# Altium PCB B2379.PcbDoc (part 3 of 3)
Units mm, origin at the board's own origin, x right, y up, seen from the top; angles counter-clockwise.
Board outline 50 x 95 mm, 4 copper layers (Top Layer 1 Signal, Layer 2, Layer 3, Bottom Layer 4 Signal), stack 1.536 mm thick; 177 components, 121 nets, 523 pads, 969 vias.
Unrouted connection lines stored in the file: 25.
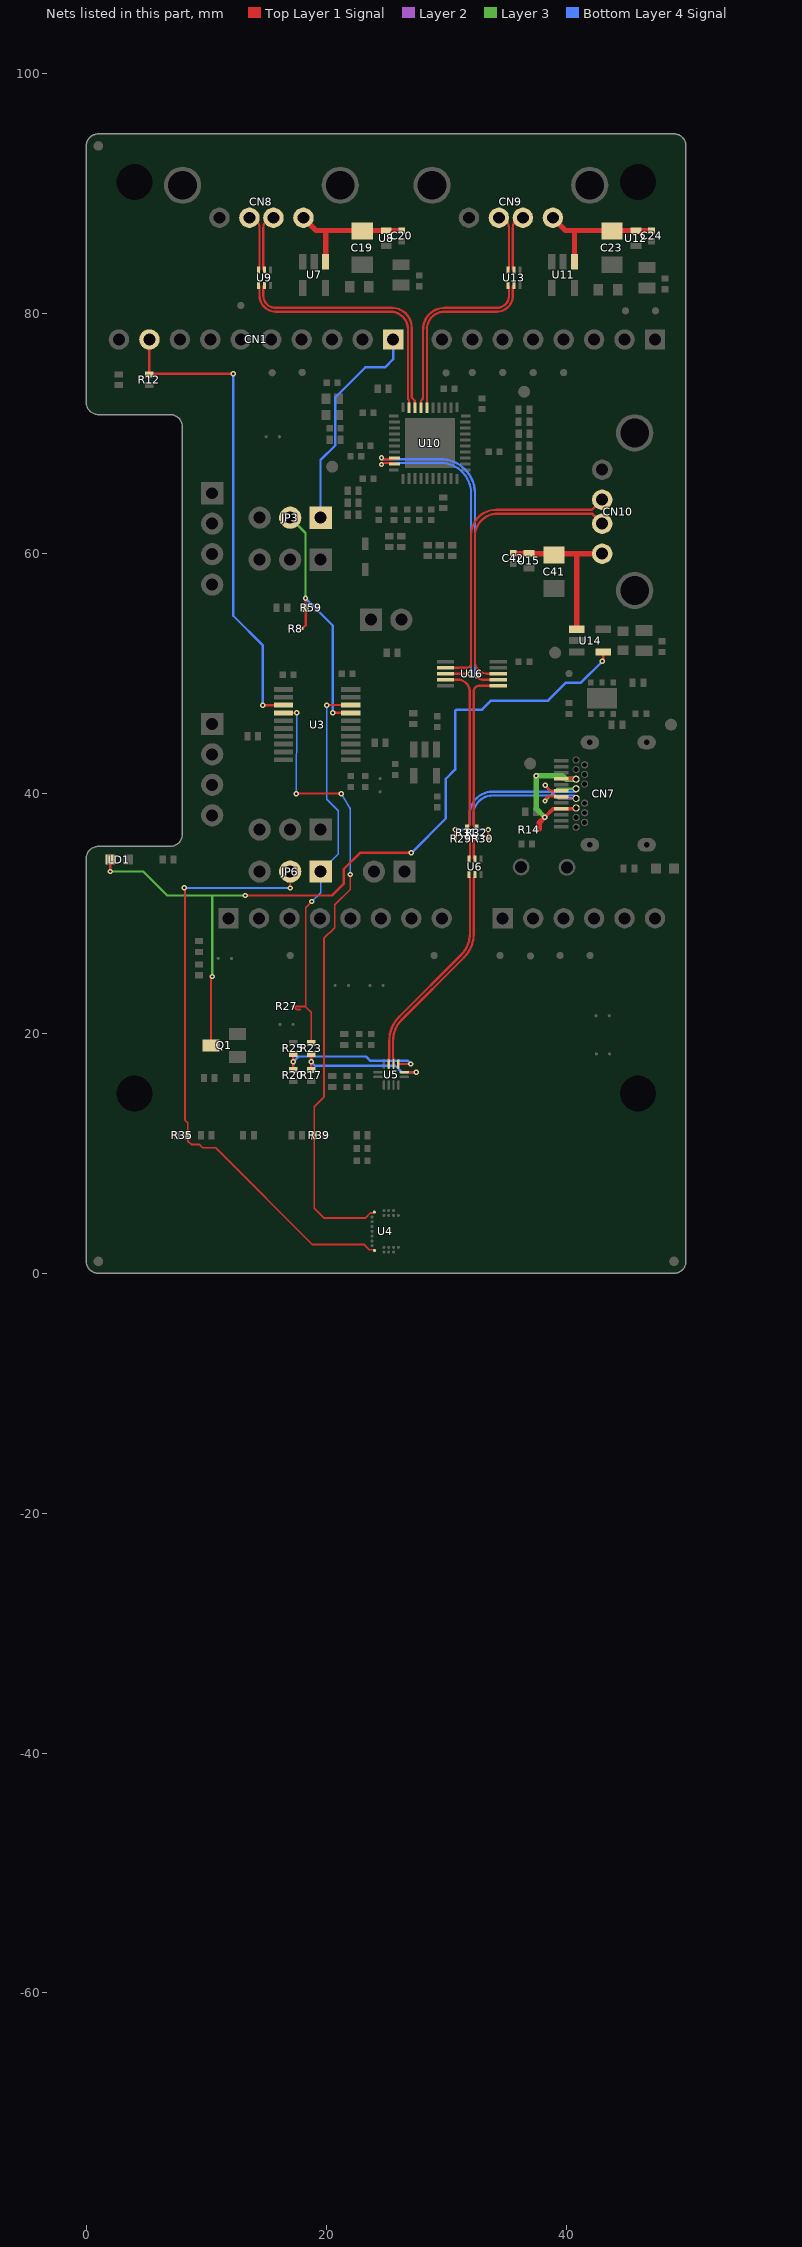
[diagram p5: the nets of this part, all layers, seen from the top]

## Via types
v1: diameter 0.45, hole 0.2, Top Layer 1 Signal to Bottom Layer 4 Signal, tented both sides, 933 vias
v2: diameter 0.45, hole 0.2, Top Layer 1 Signal to Bottom Layer 4 Signal, tented bottom, 24 vias
v3: diameter 0.45/0/0/0.45 (per signal layer), hole 0.2, Top Layer 1 Signal to Bottom Layer 4 Signal, tented both sides, 12 vias

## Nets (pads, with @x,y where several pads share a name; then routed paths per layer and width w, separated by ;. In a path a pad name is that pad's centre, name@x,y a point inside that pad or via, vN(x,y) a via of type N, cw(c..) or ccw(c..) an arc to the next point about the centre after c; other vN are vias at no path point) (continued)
SDA_1V8: JP6.1 R23.1 R27.1 U3.18 | length 33.6
  Top Layer 1 Signal w0.15: 17.827,22 17.603,22 cw(c17.603,22.15) 17.507,22.035 R27.1@17.25,22.25 18.25,22.25 18.298,22.298 ; R23.1@18.75,19.2 18.75,21.75 18.298,22.202 18.298,22.298 ; v1(18.806,31) 18.298,30.492 18.298,22.298 ; v1(20.057,47.375) U3.18@22.05,47.375
  Bottom Layer 4 Signal w0.15: v1(18.806,31) 19.54,31.734 JP6.1@19.54,33.5 21,34.96 21,38.568 20.048,39.52 20.048,47.366 v1(20.057,47.375)
SDA_D14_3V3_4: CN1.9 R12.1 U3.3 | length 40.3
  Top Layer 1 Signal w0.2: CN1.9@5.26,77.86 R12.1@5.26,74.95 5.491,74.996 cw(c5.53,74.8) 5.53,75 v1(12.25,75) ; v1(14.725,47.375) U3.3@16.45,47.375
  Bottom Layer 4 Signal w0.2: v1(12.25,75) 12.25,54.825 14.725,52.35 v1(14.725,47.375)
SDA_GPIO3_1V8: JP6.2 R35.1 U4.M2 | length 50.8
  Top Layer 1 Signal w0.15: v1@8.231,32.136 8.231,12.769 8.45,12.55 R35.1@8.45,11.5 8.45,11.025 8.475,11.025 8.75,10.75 9.409,10.75 9.686,10.473 10.777,10.473 11.25,10 18.858,2.392 23.189,2.392 23.608,1.973 23.925,1.973 23.998,1.9 U4.M2@24.025,1.9 ; v1(17,32.125) JP6.2@17,33.5
  Bottom Layer 4 Signal w0.15: v1(8.181,32.136) 8.231,32.136 8.242,32.125 v1(17,32.125)
TX_D8_3V3_4: CN1.1 JP3.1 | length 18.3
  Bottom Layer 4 Signal w0.2: JP3.1@19.54,63 19.525,63.015 19.525,67.8 20.75,69.025 20.75,73.03 23.259,75.539 24.912,75.539 25.58,76.207 CN1.1@25.58,77.86
TX_GPIO0_1V8: R39.1 U3.4 U4.B2 | length 53.2
  Top Layer 1 Signal w0.15: U3.4@16.45,46.725 17.523,46.725 v1(17.548,46.75) ; v1(17.5,40) v1(21.25,40) ; R39.1@18.897,11.46 19,11.225 19,5.436 19.828,4.608 23.27,4.608 23.689,5.027 23.925,5.027 23.998,5.1 U4.B2@24.025,5.1 ; R39.1@18.989,11.5 19.003,11.775 19.003,13.885 19.81,14.693 19.81,27.921 20.717,28.828 20.717,30.717 22,32 v1(22,33.25)
  Bottom Layer 4 Signal w0.15: v1(17.5,40) v1(17.548,46.75) ; v1(21.25,40) 21.979,38.785 cw(c21.85,38.708) 22,38.708 v1(22,33.25)
TX_GPIO0_3V3_4: JP3.2 R8.1 R59.1 U3.17 | length 21.9
  Top Layer 1 Signal w0.2: R8.1@18,53.75 18.3,54.05 18.3,55.15 18.275,55.175 v1(18.275,56.275) ; v1(20.55,46.725) U3.17@22.05,46.725
  Layer 3 w0.2: JP3.2@17,63 18.275,61.725 v1(18.275,56.275)
  Bottom Layer 4 Signal w0.2: v1(18.275,56.275) 20.55,54 v1(20.55,46.725)
USB2_ST60_3_N: R30.2 R32.2 U6.5 | length 1.9
  Top Layer 1 Signal w0.19: U6.5@32.396,34.54 cw(c32.396,34.632) 32.304,34.632 32.304,36.01 cw(c32.546,36.01) R32.2@32.545,36.252
USB2_ST60_3_P: R29.2 R31.2 U6.6 | length 1.9
  Top Layer 1 Signal w0.19: R29.2@31.747,36.25 cw(c31.747,36.01) 31.988,36.01 31.988,34.632 cw(c31.896,34.632) U6.6@31.896,34.54
USB_D_5_N: CN10.2 U16.8 | length 25
  Top Layer 1 Signal w0.19: U16.8@34.35,50 33.418,50 cw(c33.418,51.018) 32.4,51.018 32.4,51.956 32.4,57.242 32.4,61.446 cw(c34.296,61.446) 34.296,63.341 41.926,63.341 42.168,63.342 CN10.2@43.01,62.5
USB_D_5_P: CN10.3 U16.2 | length 25.5
  Top Layer 1 Signal w0.19: U16.2@29.95,50.5 31.759,50.5 ccw(c31.759,50.824) 32.083,50.824 32.083,57.242 32.083,61.577 cw(c34.165,61.577) 34.165,63.658 41.795,63.658 42.169,63.659 CN10.3@43.01,64.5
USB_H1_6_N: U9.2 U10.28 | length 21.5
  Top Layer 1 Signal w0.19: U9.2@14.85,82.35 ccw(c14.85,82.258) 14.758,82.258 14.758,81.525 ccw(c15.784,81.525) 15.784,80.5 25.487,80.5 cw(c25.487,78.852) 27.134,78.852 27.134,73.015 27.388,72.761 U10.28@27.388,72.187
USB_H1_6_P: U9.1 U10.29 | length 21.4
  Top Layer 1 Signal w0.19: U9.1@14.35,82.35 cw(c14.35,82.258) 14.442,82.258 14.442,81.525 ccw(c15.784,81.525) 15.784,80.183 25.355,80.183 cw(c25.355,78.721) 26.817,78.721 26.817,72.884 26.9,72.801 U10.29@26.9,72.175
USB_H2_6_N: U10.26 U13.2 | length 16.2
  Top Layer 1 Signal w0.19: U10.26@28.4,72.175 28.4,78.708 cw(c29.875,78.708) 28.4,78.711 cw(c29.875,78.708) 28.789,79.706 cw(c29.875,78.708) 29.875,80.183 30.36,80.183 ; 30.364,80.183 34.242,80.183 ccw(c34.242,81.5) 35.558,81.5 35.558,82.258 cw(c35.65,82.258) U13.2@35.65,82.35
USB_H2_6_P: U10.27 U13.1 | length 16.3
  Top Layer 1 Signal w0.19: U10.27@27.9,72.175 27.912,72.187 27.912,72.761 28.081,72.931 28.081,78.706 cw(c29.875,78.706) 28.082,78.753 cw(c29.875,78.706) 28.424,79.761 cw(c29.875,78.706) 29.875,80.5 34.242,80.5 ccw(c34.242,81.5) 35.241,81.5 35.241,82.258 ccw(c35.15,82.258) U13.1@35.15,82.35
USB_H_3_N: CN7.A7 CN7.B7 R30.1 | length 17.1
  Top Layer 1 Signal w0.19: v3(33.5,37) 33.5,36.31 R30.1@33.546,36.253 ; v1(38.25,40.68) 38.68,40.25 CN7.A7@39.59,40.25
  Layer 2 w0.19: v1(38.25,40.68) 39.33,39.6 CN7.B7@40.84,39.6
  Bottom Layer 4 Signal w0.19: v3(33.5,37) 32.846,37 cw(c32.846,37.562) 32.283,37.562 32.283,38.254 cw(c33.871,38.254) 32.443,38.947 cw(c33.871,38.254) 33.871,39.842 40.598,39.842 cw(c40.598,39.6) CN7.B7@40.84,39.6
USB_H_3_P: CN7.A6 CN7.B6 R29.1 | length 17.7
  Top Layer 1 Signal w0.19: R29.1@30.747,36.25 30.75,36.253 v3(30.75,37) ; v1(38.246,39.378) 38.25,39.382 38.25,39.5 38.5,39.75 CN7.A6@39.59,39.75
  Layer 3 w0.19: v1(38.246,39.378) 39.268,40.4 CN7.B6@40.84,40.4
  Bottom Layer 4 Signal w0.19: v3(30.75,37) 31.404,37 ccw(c31.404,37.562) 31.966,37.562 31.966,38.254 cw(c33.871,38.254) 33.871,40.158 40.598,40.158 ccw(c40.598,40.4) CN7.B6@40.84,40.4
USB_HUB1_6_N: CN8.2 U9.5 | length 4.9
  Top Layer 1 Signal w0.19: U9.5@14.85,83.65 cw(c14.85,83.742) 14.758,83.742 14.758,87.168 cw(c15.6,87.168) CN8.2@15.6,88.01
USB_HUB1_6_P: CN8.3 U9.6 | length 4.9
  Top Layer 1 Signal w0.19: CN8.3@13.6,88.01 cw(c13.6,87.169) 14.441,87.169 14.441,83.741 cw(c14.35,83.741) U9.6@14.35,83.65
USB_HUB2_6_N: CN9.2 U13.5 | length 4.9
  Top Layer 1 Signal w0.19: U13.5@35.65,83.65 cw(c35.65,83.742) 35.558,83.742 35.558,87.168 cw(c36.4,87.168) CN9.2@36.4,88.01
USB_HUB2_6_P: CN9.3 U13.6 | length 4.9
  Top Layer 1 Signal w0.19: CN9.3@34.4,88.01 cw(c34.4,87.169) 35.241,87.169 35.241,83.741 cw(c35.15,83.741) U13.6@35.15,83.65
USB_HUB_N: U10.38 U16.7 | length 27.9
  Top Layer 1 Signal w0.19: v3(24.616,68.016) ccw(c24.748,68.016) 24.748,67.884 25.609,67.884 ccw(c25.609,67.975) U10.38@25.7,67.975 ; v3(32.53,49.8) 32.689,49.641 ccw(c33.03,49.983) 33.03,49.5 U16.7@34.35,49.5
  Bottom Layer 4 Signal w0.19: v3(24.616,68.016) ccw(c24.746,68.016) 24.746,67.886 29.543,67.886 cw(c29.543,65.029) 32.4,65.029 32.4,49.93 v3(32.53,49.8)
USB_HUB_P: U10.39 U16.3 | length 27.2
  Top Layer 1 Signal w0.19: v3(24.616,67.439) cw(c24.744,67.439) 24.744,67.567 25.609,67.567 cw(c25.609,67.475) U10.39@25.7,67.475 ; U16.3@29.95,50 v3(31.953,50)
  Bottom Layer 4 Signal w0.19: v3(24.616,67.439) cw(c24.746,67.439) 24.746,67.569 29.543,67.569 cw(c29.543,65.029) 32.083,65.029 v3@32.083,50
USB_SCL_1V8_3: R20.1 R25.2 U5.7 | length 12.7
  Top Layer 1 Signal w0.2: R20.1@17.25,16.95 v1(17.25,17.626) R25.2@17.25,18.302 ; U5.7@26.015,17.45 v1(27.065,17.45)
  Bottom Layer 4 Signal w0.2: v1(17.25,17.626) 17.701,18.077 23.315,18.077 23.657,17.735 26.78,17.735 v1(27.065,17.45)
USB_SDA_1V8_3: R17.1 R23.2 U5.6 | length 11.2
  Top Layer 1 Signal w0.2: R17.1@18.75,16.95 v1(18.75,17.625) R23.2@18.75,18.3 ; U5.6@26.798,16.775 27.475,16.775 v1(27.5,16.75)
  Bottom Layer 4 Signal w0.2: v1(18.75,17.625) 19.075,17.3 25.765,17.3 26.315,16.75 v1(27.5,16.75)
USB_ST60_E_3_N: U5.8 U6.2 | length 18.4
  Top Layer 1 Signal w0.19: U5.8@25.615,17.45 25.613,17.452 25.613,17.868 ccw(c25.546,17.868) 25.593,17.916 cw(c25.641,17.964) 25.573,17.964 25.573,19.373 cw(c28.113,19.373) 26.317,21.169 31.504,26.356 ccw(c29.574,28.286) 32.304,28.286 32.304,32.908 cw(c32.461,32.908) 32.35,33.019 ccw(c32.239,33.13) 32.396,33.13 U6.2@32.396,33.24
USB_ST60_E_3_P: U5.9 U6.1 | length 18.4
  Top Layer 1 Signal w0.19: U5.9@25.215,17.45 25.217,17.452 25.217,17.868 cw(c25.284,17.868) 25.237,17.916 ccw(c25.189,17.964) 25.257,17.964 25.257,19.374 cw(c28.11,19.374) 26.092,21.392 31.243,26.543 ccw(c29.447,28.339) 31.987,28.339 31.987,32.91 ccw(c31.832,32.91) 31.941,33.02 cw(c32.051,33.129) 31.896,33.129 U6.1@31.896,33.24
USB_ST60_N: R32.1 U16.6 | length 13.7
  Top Layer 1 Signal w0.19: R32.1@32.545,37.252 cw(c32.545,37.501) 32.296,37.501 32.296,48.5 cw(c32.796,48.5) 32.796,49 U16.6@34.35,49
USB_ST60_P: R31.1 U16.4 | length 14
  Top Layer 1 Signal w0.19: U16.4@29.95,49.5 30.979,49.5 cw(c30.979,48.5) 31.979,48.5 31.979,37.494 cw(c31.737,37.494) R31.1@31.737,37.252
VBUS_D_5: C41.2 C42.2 CN10.1 U14.1 U15.1 | length 13.6
  Top Layer 1 Signal w0.45: C42.2@35.6,60.05 35.625,60.05 35.675,60 40.93,60 CN10.1@43.01,60 ; U14.1@40.9,53.7 40.9,59.884
VBUS_D_EN_N: LD1.2 Q1.3 U14.4 | length 69.8
  Top Layer 1 Signal w0.2: v1(2,33.5) 2,34.125 LD1.2@2,34.5 ; Q1.3@10.4,19 10.4,24.65 v1(10.5,24.75) ; v1(13.25,31.5) 20.493,31.5 21.455,32.462 21.455,33.689 22.816,35.05 v1(27.102,35.05) ; v1(43.017,51.025) 43.1,51.108 U14.4@43.1,51.8
  Layer 3 w0.2: v1(2,33.5) 4.75,33.5 6.75,31.5 10.5,31.5 ; v1(10.5,24.75) 10.5,31.5 ; v1(13.25,31.5) 10.5,31.5
  Bottom Layer 4 Signal w0.2: v1(27.102,35.05) 29.975,37.923 29.975,41.225 30.75,42 30.75,46.883 30.867,47 33,47 33.75,47.75 38.5,47.75 40,49.25 41.242,49.25 v1(43.017,51.025)
VBUS_HUB1_6: C19.2 C20.2 CN8.1 U7.1 U8.1 | length 11.1
  Top Layer 1 Signal w0.45: CN8.1@18.1,88.01 19.16,86.95 C20.2@26.3,86.95 ; U7.1@19.95,84.35 19.95,86.847
VBUS_HUB2_6: C23.2 C24.2 CN9.1 U11.1 U12.1 | length 11.2
  Top Layer 1 Signal w0.45: CN9.1@38.9,88.01 39.96,86.95 C24.2@47.125,86.95 ; U11.1@40.7,84.35 40.7,86.888
VBUS_POWER_3: CN7.A4 CN7.A9 CN7.B4 CN7.B9 R14.1 | length 12.7
  Top Layer 1 Signal w0.3: 37.7,37 37.75,37.05 ; v1(38.224,38.026) 38.948,38.75 CN7.A4@39.59,38.75 40.79,38.75 CN7.B9@40.84,38.8 ; CN7.A9@39.59,41.25 40.79,41.25 CN7.B4@40.84,41.2
  Top Layer 1 Signal w0.45: 37.75,37.05 37.75,37.552 v1(38.224,38.026)
  Layer 3 w0.45: v1(38.224,38.026) 37.5,38.75 v1(37.5,41.5) 39.7,41.5 40,41.2 CN7.B4@40.84,41.2
pads on no net: CN1.8 CN2.1 CN2.2 CN4.5 CN4.6 CN7.A2 CN7.A3 CN7.A10 CN7.A11 CN7.B2 CN7.B3 CN7.B10 CN7.B11 HW3.1 HW4.1 HW5.1 R61.1 R61.2 R62.1 R62.2 U1.5 U6.4 U9.4 U10.21 U10.22 U10.23 U10.24 U13.4

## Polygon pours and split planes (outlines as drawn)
GND on Layer 3 "GND_L03_P028" (solid, remove dead copper, pour order 28): 1,0 cw(c1,1) 0,1 0,34.597 cw(c1,34.597) 1,35.597 7,35.597 ccw(c7,36.597) 8,36.597 8,70.597 ccw(c7,70.597) 7,71.597 1,71.597 cw(c1,72.597) 0,72.597 0,94 cw(c1,94) 1,95 49,95 cw(c49,94) 50,94 50,1 cw(c49,1) 49,0
GND on Top Layer 1 Signal "GND_L01_P026" (solid, remove dead copper, pour order 26): 1,0 cw(c1,1) 0,1 0,34.597 cw(c1,34.597) 1,35.597 7,35.597 ccw(c7,36.597) 8,36.597 8,70.597 ccw(c7,70.597) 7,71.597 1,71.597 cw(c1,72.597) 0,72.597 0,94 cw(c1,94) 1,95 49,95 cw(c49,94) 50,94 50,1 cw(c49,1) 49,0
GND on Layer 2 "GND_L02_P027" (solid, remove dead copper, pour order 27): 1,0 cw(c1,1) 0,1 0,34.597 cw(c1,34.597) 1,35.597 7,35.597 ccw(c7,36.597) 8,36.597 8,70.597 ccw(c7,70.597) 7,71.597 1,71.597 cw(c1,72.597) 0,72.597 0,94 cw(c1,94) 1,95 49,95 cw(c49,94) 50,94 50,1 cw(c49,1) 49,0
GND on Bottom Layer 4 Signal "GND_L04_P029" (solid, remove dead copper, pour order 29): 1,0 cw(c1,1) 0,1 0,34.597 cw(c1,34.597) 1,35.597 7,35.597 ccw(c7,36.597) 8,36.597 8,70.597 ccw(c7,70.597) 7,71.597 1,71.597 cw(c1,72.597) 0,72.597 0,94 cw(c1,94) 1,95 49,95 cw(c49,94) 50,94 50,1 cw(c49,1) 49,0

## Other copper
Top Layer 1 Signal:
  drawing of 20 lines, arcs and shapes, not listed
  text "1" at 4.75,28.75 h0.75
  text ".Layer_Name" at -11.637,-69.423 h3
  text ".GTL" at 30.058,-69.423 h3
Layer 2:
  pour cut-out: 38.262,41.037 38.276,41.039 38.364,41.022 38.385,41.007 38.411,41.002 38.486,40.952 38.5,40.931 38.522,40.916 38.572,40.841 38.577,40.816 38.591,40.794 38.609,40.706 38.604,40.68 38.609,40.655 38.609,40.654 39.428,39.835 40.477,39.835 40.514,39.89 40.536,39.904 40.55,39.926 40.65,39.992 40.675,39.997 40.697,40.012 40.814,40.035 40.84,40.03 40.866,40.035 40.983,40.012 41.005,39.997 41.03,39.992 41.13,39.926 41.144,39.904 41.166,39.89 41.232,39.79 41.237,39.765 41.252,39.743 41.275,39.626 41.27,39.6 41.275,39.574 41.252,39.457 41.237,39.435 41.232,39.41 41.166,39.31 41.144,39.296 41.13,39.274 41.03,39.208 41.005,39.203 40.983,39.188 40.866,39.165 40.84,39.17 40.814,39.165 40.697,39.188 40.675,39.203 40.65,39.208 40.55,39.274 40.536,39.296 40.514,39.31 40.477,39.365 39.33,39.365 39.306,39.375 39.28,39.375 39.207,39.405 39.189,39.424 39.164,39.434 38.277,40.322 38.276,40.322 38.25,40.327 38.224,40.322 38.136,40.339 38.115,40.354 38.089,40.359 38.014,40.408 38,40.43 37.978,40.445 37.928,40.519 37.923,40.545 37.909,40.567 37.891,40.655 37.896,40.68 37.891,40.706 37.909,40.794 37.923,40.816 37.928,40.841 37.978,40.916 38,40.931 38.014,40.952 38.089,41.002 38.115,41.007 38.136,41.022 38.224,41.039 38.238,41.037 38.25,41.042
  pour cut-out: 30.467,36.529 31.028,36.529 31.029,36.529 31.029,35.969 30.468,35.969
  pour cut-out: 33.246,35.97 33.248,35.971 33.248,36.53 33.801,36.53 33.802,36.531 33.808,36.526 33.808,35.972
  pour cut-out: 32.246,36.194 32.245,36.195 32.245,36.533 32.818,36.533 32.814,36.529 32.814,35.971 32.399,35.971
  pour cut-out: 32.256,36.975 32.254,36.973 32.255,36.973 32.815,36.973 32.815,37.532 32.813,37.531 32.409,37.531 32.391,37.512 32.256,37.309
  pour cut-out: 32.011,36.533 32.027,36.425 32.027,36.195 31.879,35.973 31.789,35.973 31.604,35.973 31.457,35.973 31.457,36.531 31.458,36.532 32.012,36.532
  pour cut-out: 31.457,37.53 31.866,37.531 32.017,37.308 32.017,37.122 32.017,36.975 31.459,36.975 31.458,36.976 31.458,37.531
  pour cut-out: 29.952,50.356 29.225,50.355 29.225,50.356 29.225,50.652 30.674,50.652 30.676,50.651 30.674,50.65 30.674,50.355
  pour cut-out: 29.952,49.852 29.225,49.85 29.225,49.852 29.225,50.147 30.674,50.147 30.676,50.146 30.674,50.145 30.674,49.85
  pour cut-out: 29.953,49.355 29.227,49.354 29.227,49.355 29.227,49.651 30.676,49.651 30.677,49.65 30.676,49.649 30.676,49.354
  pour cut-out: 34.354,49.852 33.628,49.851 33.628,49.852 33.628,50.148 35.077,50.148 35.078,50.147 35.077,50.146 35.077,49.851
  pour cut-out: 34.352,49.352 33.625,49.351 33.625,49.352 33.625,49.648 35.075,49.648 35.076,49.647 35.075,49.646 35.075,49.351
  pour cut-out: 34.352,48.853 33.625,48.852 33.625,48.853 33.625,49.149 35.075,49.149 35.076,49.148 35.075,49.147 35.075,48.852
  text "2" at 4.725,27.413 h0.75
  text ".G1" at 30.083,-69.498 h3
  text ".Layer_Name" at -11.612,-69.548 h3
Layer 3:
  pour cut-out: 40.983,40.812 41.005,40.797 41.03,40.792 41.13,40.726 41.144,40.704 41.166,40.69 41.232,40.59 41.237,40.565 41.252,40.543 41.275,40.426 41.27,40.4 41.275,40.374 41.252,40.257 41.237,40.235 41.232,40.21 41.166,40.11 41.144,40.096 41.13,40.074 41.03,40.008 41.005,40.003 40.983,39.988 40.866,39.965 40.84,39.97 40.814,39.965 40.697,39.988 40.675,40.003 40.65,40.008 40.55,40.074 40.536,40.096 40.514,40.11 40.477,40.165 39.365,40.165 38.605,39.405 38.605,39.404 38.6,39.378 38.605,39.352 38.587,39.265 38.573,39.243 38.568,39.217 38.518,39.143 38.496,39.128 38.482,39.106 38.407,39.057 38.381,39.051 38.36,39.037 38.272,39.019 38.246,39.024 38.22,39.019 38.132,39.037 38.111,39.051 38.085,39.057 38.01,39.106 37.996,39.128 37.974,39.143 37.924,39.217 37.919,39.243 37.905,39.265 37.887,39.352 37.892,39.378 37.887,39.404 37.905,39.492 37.919,39.514 37.924,39.539 37.974,39.614 37.996,39.628 38.01,39.65 38.085,39.7 38.111,39.705 38.132,39.72 38.22,39.737 38.234,39.734 38.246,39.74 38.259,39.734 38.272,39.737 38.273,39.737 39.102,40.566 39.126,40.576 39.145,40.595 39.217,40.625 39.244,40.625 39.268,40.635 40.477,40.635 40.514,40.69 40.536,40.704 40.55,40.726 40.65,40.792 40.675,40.797 40.697,40.812 40.814,40.835 40.84,40.83 40.866,40.835
  text "3" at 5.153,25.445 h0.75
  text ".Layer_Name" at -11.612,-69.498 h3
  text ".G2" at 30.083,-69.548 h3
Bottom Layer 4 Signal:
  pour cut-out: 244 vertices and 0 holes, not listed, extent 30.391,36.641 41.275,40.835
  pour cut-out: 177 vertices and 0 holes, not listed, extent 24.768,2.341 26.062,14.861
  pour cut-out: 177 vertices and 0 holes, not listed, extent 24.257,49.441 32.889,68.377
  text "4" at 5.17,24.063 h0.75
  text ".GBL" at 18.879,-69.53 h3
  text ".Layer_Name" at 60.193,-69.53 h3
Multi-Layer:
  pour cut-out: 4.187,23.5 4.187,30 5.687,30 5.687,23.5

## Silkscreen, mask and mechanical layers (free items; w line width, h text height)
Top Overlay:
  drawing of 61 lines, arcs and shapes, not listed
  text "HUB DEVICE 1" at 5.5,84.516 h1.4
  text "HUB DEVICE 2" at 26.5,84.516 h1.4
  text "I" at 1.206,84.439 h8
  text "C" at 7.369,80.586 h5
  text "H" at 1.061,79.835 h8
  text "B2379B" at 6.45,73.275 h2
  text "DEVICE" at 40.5,72.266 h1.4
  text "EXT" at 9.5,69.084 h1.4
  text "UART" at 9.5,68 h1.4
  text "UART" at 15.5,66.025 h1.4
  text "+3V3" at 12,66 h1.2
  text "EXT" at 14.5,65 h1.2
  text "MCU" at 17.35,65 h1.2
  text "Tx" at 11.9,62.25 h1.2
  text "Rx" at 11.875,59.375 h1.2
  text "HUB Disable" at 22.1,56 h1.2
  text "GND" at 9.5,55 h1.2
  text "L" at 33.281,54.204 h8
  text "EXT" at 9.675,49.884 h1.4
  text "I2C" at 9.75,48.75 h1.4
  text "+3V3" at 12,46.75 h1.2
  text "SDA" at 12.05,42.832 h1.2
  text "SCL" at 12.05,40.348 h1.2
  text "I2C" at 16.075,39.975 h1.4
  text "EXT" at 14.5,39 h1.2
  text "MCU" at 17.25,39 h1.2
  text "GND" at 9.5,35.75 h1.2
  text "NUCLEO 5V" at 22,35.5 h1.4
  text "5V" at 33.875,33.55 h1.2
  text "GND" at 41.2,33.55 h1.2
  text "LINK_STATUS" at 1.375,32.575 h1.4
  text "POWER ON" at 42.8,31.75 h1.4
  text "3V3" at 18.55,27.436 h1.2
  text "5V" at 21.25,27.436 h1.2
  text "GND" at 23.375,27.436 h1.2
  text "GND" at 25.95,27.436 h1.2
  text "Product configured" at 37.875,24.313 h1.4
  text "as R61/R62 mounted" at 36.975,23.066 h1.4
  text "X-NUCLEO-60L1A1" at 28.625,21.241 h1.4
  text "Local" at 45.025,21.089 h1.4
  text "XN$60L1A1B" at 30.15,20.055 h1.4
  text "E" at 2.617,18.501 h8
  text "X-NUCLEO-60R1A1" at 28.775,18.091 h1.4
  text "Remote" at 45.05,18.014 h1.4
  text "XN$60R1A1B" at 30.225,16.88 h1.4
  text "ST60 reserved area" at 33.875,7.516 h1.4
  text "G" at 3.668,7.129 h5
  text "S" at 8.75,6.5 h5
  text "R 006-001386" at 12.575,5.625 h1.2
  text "NOT FCC APPROVED FOR RESALE" at 1.625,4.3 h1.6 r90
  text "T" at 37.822,1.965 h8
  text "J" at 6.632,1.411 h10
  text "FOR EVALUATION ONLY" at 2.525,0.55 h1.4
  text ".Layer_Name" at -11.612,-69.498 h3
  text ".GTO" at 30.083,-69.498 h3
Bottom Overlay:
  text ".GBO" at 18.879,-69.53 h2
  text ".Layer_Name" at 60.193,-69.53 h2
Top Paste:
  text ".Layer_Name" at -11.639,-69.488 h3
  text ".GTP" at 30.055,-69.488 h3
Bottom Paste:
  text ".GBP" at 18.77,-69.515 h3
  text ".Layer_Name" at 60.084,-69.515 h3
Top Solder:
  region: 4.187,23.5 4.187,30 5.687,30 5.687,23.5
  text ".Layer_Name" at -11.614,-69.563 h3
  text ".GTS" at 30.08,-69.563 h3
Bottom Solder:
  region: 24.525,13.625 24.525,12.625 23.525,12.625 23.525,13.625
  region: 25.35,13.625 25.35,12.625 25.15,12.625 25.15,13.625
  region: 25.475,10.625 25.475,11.625 25.675,11.625 25.675,10.625
  region: 26.3,10.625 26.3,11.625 27.3,11.625 27.3,10.625
  region: 4.187,23.5 4.187,30 5.687,30 5.687,23.5
  lines w0.3: 16.5,2.3 25,2.25 33.475,2.3 ; 25,0 25,5.5 25,10
  text ".GBS" at 18.795,-69.59 h3
  text ".Layer_Name" at 60.109,-69.59 h3
M1-Board Shape:
  lines w0.05: 17.25,16.167 17.25,16.167
  lines w0.1: 0,34.597 cw(c1,34.597) 1,35.597 ; 0,34.597 cw(c1,34.597) 1,35.597 ; 0,34.597 0,1 ccw(c1,1) 1,0 18.5,0 30,0 49,0 ccw(c49,1) 50,1 50,94 ; 0,72.597 ccw(c1,72.597) 1,71.597 ; 0,72.597 ccw(c1,72.597) 1,71.597 ; 0,72.597 0,94 ; 0,94 cw(c1,94) 1,95 ; 0,94 cw(c1,94) 1,95 ; 1,35.597 7,35.597 ; 1,71.597 7,71.597 ; 1,95 49,95 ; 7,35.597 ccw(c7,36.597) 8,36.597 ; 7,35.597 ccw(c7,36.597) 8,36.597 ; 7,71.597 cw(c7,70.597) 8,70.597 ; 7,71.597 cw(c7,70.597) 8,70.597 ; 8,36.597 8,70.597 ; 49,95 cw(c49,94) 50,94 ; 49,95 cw(c49,94) 50,94
M2-Board Dimensions:
  text ".Layer_Name" at -11.612,-69.498 h3
  text ".GM2" at 30.083,-69.498 h3
M3-Top Dimensions:
  lines w0.1: 49.828,94.753 55.093,100 63.531,100
  text "r=1mmx8" at 55.603,100.477 h1.4
M5-Top Constraints:
  circle w0.254: c4,91 r2.752
  circle w0.254: c46,91 r2.75
  lines w0.254: -30.14,18.73 51.42,18.73 51.42,88.73 -30.14,88.73 -30.14,18.73
  text "M1136 C-04 NUCLEO-L476RG" at -26.957,42.858 h1 r90
M14-Top Assembly:
  text ".Layer_Name" at -11.612,-69.498 h3
  text ".GM14" at 30.083,-69.498 h3
M15-Bottom Assembly:
  text ".GM15" at 18.879,-69.53 h3
  text ".Layer_Name" at 60.193,-69.53 h3
M16-Top Courtyard:
  lines w0.05: 20,0 30.002,0 30.002,9.002 20,9.002 20,0
Drill Drawing:
  drawing of 374 lines, arcs and shapes, not listed
  text "« THE COMPONENTS WITH PLATED THROUGH HOLE (PTH) MAY BE WELDED (CABLED) IN \"PIN-IN-PASTE\" MODE (IF NECESSARY) »" at 92.369,103.254 h3.5
  text "PCB SPECIFICATIONS :" at 76.114,97.194 h3
  text "**Plating type :" at 193.164,96.844 h2.5
  text "X ECU104" at 115.739,93.327 h3
  text "TG-170" at 131.239,93.327 h3
  text "TG-150" at 148.339,93.327 h3
  text "TG-140" at 165.489,93.327 h3
  text "TG-155" at 179.889,93.327 h3
  text "FR-4" at 108.375,93.294 h3
  text "A.   MATERIAL :" at 76.114,93.194 h3
  text "lead Gold" at 199.889,92.369 h2.5
  text "B.   MATERIAL FAMILY :" at 76.114,90.194 h3
  text "N/A" at 114.614,90.194 h3
  text "C.   SOLDERMASK COLOR :" at 76.114,87.194 h3
  text "GREEN" at 114.614,87.194 h3
  text "WHITE" at 131.114,87.194 h3
  text "RED" at 149.364,87.194 h3
  text "X  Blue ink PANTONE 2955" at 165.364,87.194 h3
  text "D.   SILKSCREEN COLOR :" at 76.114,84.194 h3
  text "X  WHITE" at 114.614,84.194 h3
  text "YELLOW" at 131.114,84.194 h3
  text "BLACK" at 149.364,84.194 h3
  text "Blue ink PANTONE 2955" at 165.364,84.194 h3
  text "E.   SURFACE FINISH :" at 76.114,81.194 h3
  text "X  ENIG" at 114.614,81.194 h3
  text "IMMERSION SILVER" at 131.114,81.194 h3
  text "IMMERSION TIN" at 165.364,81.194 h3
  text "HASL" at 114.614,78.194 h3
  text "HASL (PB-FREE)" at 131.114,78.194 h3
  text "GOLDEN FINGER" at 165.364,78.194 h3
  text "F.   IMPEDANCE CONTROL :" at 76.114,75.194 h3
  text "NO" at 114.614,75.194 h3
  text "X  YES  (SEE IMPEDANCE TABLE FOR DETAIL INFORMATION)" at 131.114,75.194 h3
  text "G.   STACK-UP :" at 76.114,69.844 h3
  text "SEE LAYER STACK-UP SEQUENCE FOR OVERALL THICKNESS." at 114.614,69.844 h3
  text "AREL" at 76.966,61.381 h1.52
  text "Name" at 83.528,61.381 h1.52
  text "Material" at 99.799,61.381 h1.52
  text "Thickness" at 114.041,61.381 h1.52
  text "Constant" at 123.145,61.381 h1.52
  text "Board Layer Stack" at 131.572,61.381 h1.52
  text "Top Overlay" at 83.528,58.333 h1.52
  text "Top Solder" at 83.528,55.285 h1.52
  text "SM-003" at 99.799,55.285 h1.52
  text "1.00mil" at 114.041,55.285 h1.52
  text "4" at 123.145,55.285 h1.52
  text "1" at 76.966,52.237 h1.52
  text "Top Layer 1 Signal" at 83.528,52.237 h1.52
  text "Cu EXT" at 99.799,52.237 h1.52
  text "1.38mil" at 114.041,52.237 h1.52
  text "Dielectric 1" at 83.528,49.189 h1.52
  text "2 x 7628" at 99.798,49.189 h1.52
  text "14.17mil" at 114.041,49.189 h1.52
  text "4.6" at 123.145,49.189 h1.52
  text "2" at 76.964,46.141 h1.52
  text "Layer 2" at 83.528,46.141 h1.52
  text "CF-004" at 99.799,46.141 h1.52
  text "0.71mil" at 114.041,46.141 h1.52
  text "Core" at 83.528,43.093 h1.52
  text "CORE- 6 X 7628M" at 99.799,43.093 h1.52
  text "27.95mil" at 114.04,43.093 h1.52
  text "4.4" at 123.145,43.093 h1.52
  text "3" at 76.966,40.045 h1.52
  text "Layer 3" at 83.528,40.045 h1.52
  text "CF-004" at 99.799,40.045 h1.52
  text "0.71mil" at 114.041,40.045 h1.52
  text "Dielectric 2" at 83.528,36.997 h1.52
  text "2 x 7628" at 99.798,36.997 h1.52
  text "14.17mil" at 114.041,36.997 h1.52
  text "4.6" at 123.145,36.997 h1.52
  text "4" at 76.966,33.949 h1.52
  text "Bottom Layer 4 Signal" at 83.528,33.949 h1.52
  text "Cu EXT" at 99.799,33.949 h1.52
  text "1.38mil" at 114.041,33.949 h1.52
  text "Bottom Solder" at 83.528,30.901 h1.52
  text "SM-003" at 99.799,30.901 h1.52
  text "1.00mil" at 114.041,30.901 h1.52
  text "4" at 123.145,30.901 h1.52
  text "Bottom Overlay" at 83.528,27.853 h1.52
  text "Total board thickness:" at 76.966,24.805 h1.52
  text "62.47mil" at 114.041,24.805 h1.52
  text "Symbol" at 76.921,18.679 h1.83
  text "Count" at 84.081,18.679 h1.83
  text "Hole Size" at 92.175,18.679 h1.83
  text "Plated" at 106.846,18.679 h1.83
  text "Hole Type" at 113.132,18.679 h1.83
  text "Drill Layer Pair" at 122.284,18.679 h1.83
  text "Via/Pad" at 150.127,18.679 h1.83
  text "Pad Shape" at 157.626,18.679 h1.83
  text "Template" at 167.422,18.679 h1.83
  text "Description" at 191.92,18.679 h1.83
  text "Hole Tolerance (-)" at 201.758,18.679 h1.83
  text "Hole Length" at 216.646,18.679 h1.83
  text "Routed Path Length" at 230.56,18.679 h1.83
  text "Via Feature" at 246.769,18.679 h1.83
  text "Via Type" at 264.225,18.679 h1.83
  text "945" at 84.081,15.525 h1.52
  text "0.200mm (7.87mil)" at 92.175,15.525 h1.52
  text "PTH" at 106.846,15.525 h1.52
  text "Round" at 113.132,15.525 h1.52
  text "Top Layer 1 Signal - Bottom Layer 4 Signal" at 122.284,15.525 h1.52
  text "Via" at 150.127,15.525 h1.52
  text "Rounded" at 157.626,15.525 h1.52
  text "(Mixed)" at 167.422,15.525 h1.52
  text "(Mixed)" at 191.92,15.525 h1.52
  text "-" at 216.646,15.525 h1.52
  text "-" at 230.56,15.525 h1.52
  text "24" at 84.081,12.371 h1.52
  text "0.200mm (7.87mil)" at 92.175,12.371 h1.52
  text "PTH" at 106.846,12.371 h1.52
  text "Round" at 113.132,12.371 h1.52
  text "Top Layer 1 Signal - Bottom Layer 4 Signal" at 122.284,12.371 h1.52
  text "Via" at 150.127,12.371 h1.52
  text "Rounded" at 157.626,12.371 h1.52
  text "v45h20m-45mx0" at 167.422,12.371 h1.52
  text "-" at 216.646,12.371 h1.52
  text "-" at 230.56,12.371 h1.52
  text "Filling Both, Capping Both" at 246.769,12.371 h1.52
  text "Type 7" at 264.225,12.371 h1.52
  text "14" at 84.081,9.217 h1.52
  text "0.400mm (15.75mil)" at 92.175,9.217 h1.52
  text "PTH" at 106.846,9.217 h1.52
  text "Round" at 113.132,9.217 h1.52
  text "Top Layer 1 Signal - Bottom Layer 4 Signal" at 122.284,9.217 h1.52
  text "Pad" at 150.127,9.217 h1.52
  text "Rounded" at 157.626,9.217 h1.52
  text "c60h40m70" at 167.422,9.217 h1.52
  text "-" at 216.646,9.217 h1.52
  text "-" at 230.56,9.217 h1.52
  text "3" at 84.081,6.063 h1.52
  text "0.450mm (17.72mil)" at 92.175,6.063 h1.52
  text "PTH" at 106.846,6.063 h1.52
  text "Slot" at 113.132,6.063 h1.52
  text "Top Layer 1 Signal - Bottom Layer 4 Signal" at 122.284,6.063 h1.52
  text "Pad" at 150.127,6.063 h1.52
  text "Rounded" at 157.626,6.063 h1.52
  text "r155_115h45_85r57m165_125(Tol-5)" at 167.422,6.063 h1.52
  text "0.050mm (1.97mil)" at 201.758,6.063 h1.52
  text "0.850mm (33.47mil)" at 216.646,6.063 h1.52
  text "0.400mm (15.75mil)" at 230.56,6.063 h1.52
  text "1" at 84.081,2.908 h1.52
  text "0.450mm (17.72mil)" at 92.175,2.908 h1.52
  text "PTH" at 106.846,2.908 h1.52
  text "Slot" at 113.132,2.908 h1.52
  text "Top Layer 1 Signal - Bottom Layer 4 Signal" at 122.284,2.908 h1.52
  text "Pad" at 150.127,2.908 h1.52
  text "Rounded" at 157.626,2.908 h1.52
  text "r155_115h45_85r57m165_125" at 167.422,2.908 h1.52
  text "0.850mm (33.47mil)" at 216.646,2.908 h1.52
  text "0.400mm (15.75mil)" at 230.56,2.908 h1.52
  text "70" at 84.081,-0.246 h1.52
  text "1.000mm (39.37mil)" at 92.175,-0.246 h1.52
  text "PTH" at 106.846,-0.246 h1.52
  text "Round" at 113.132,-0.246 h1.52
  text "Top Layer 1 Signal - Bottom Layer 4 Signal" at 122.284,-0.246 h1.52
  text "Pad" at 150.127,-0.246 h1.52
  text "(Mixed)" at 157.626,-0.246 h1.52
  text "(Mixed)" at 167.422,-0.246 h1.52
  text "-" at 216.646,-0.246 h1.52
  text "-" at 230.56,-0.246 h1.52
  text "6" at 84.081,-3.4 h1.52
  text "2.400mm (94.49mil)" at 92.175,-3.4 h1.52
  text "PTH" at 106.846,-3.4 h1.52
  text "Round" at 113.132,-3.4 h1.52
  text "Top Layer 1 Signal - Bottom Layer 4 Signal" at 122.284,-3.4 h1.52
  text "Pad" at 150.127,-3.4 h1.52
  text "Rounded" at 157.626,-3.4 h1.52
  text "c310h240m330" at 167.422,-3.4 h1.52
  text "-" at 216.646,-3.4 h1.52
  text "-" at 230.56,-3.4 h1.52
  text "4" at 84.081,-6.554 h1.52
  text "3.000mm (118.11mil)" at 92.175,-6.554 h1.52
  text "PTH" at 106.846,-6.554 h1.52
  text "Round" at 113.132,-6.554 h1.52
  text "Top Layer 1 Signal - Bottom Layer 4 Signal" at 122.284,-6.554 h1.52
  text "Pad" at 150.127,-6.554 h1.52
  text "Rounded" at 157.626,-6.554 h1.52
  text "c0h300m310" at 167.422,-6.554 h1.52
  text "-" at 216.646,-6.554 h1.52
  text "-" at 230.56,-6.554 h1.52
  text "1067 Total" at 84.081,-9.708 h1.52
  text "Slot definitions :" at 76.921,-11.916 h1.52
  text "Routed Path Length" at 87.315,-11.916 h1.52
  text "= Calculated from tool start centre position to tool end centre position." at 100.192,-11.916 h1.52
  text "Hole Length" at 87.315,-13.178 h1.52
  text "= Routed Path Length + Tool Size = Slot length as defined in the PCB layout" at 95.411,-13.178 h1.52
  text ".Layer_Name" at -11.612,-69.498 h3
  text ".DRL" at 30.083,-69.498 h3
M20-Top Sheet Box:
  circle w0.254: c66.392,-76.219 r1.3
  region: 51.914,-77.312 41.158,-77.312 42.151,-74.819 50.009,-74.819 50.458,-74.06 52.666,-76.608
  region: 65.917,-68.982 50.39,-68.982 49.696,-70.758 48.485,-71.983 47.088,-70.123 47.088,-68.472 48.231,-67.075 49.667,-66.696 65.917,-66.696
  lines w0.254: 42.151,-74.819 50.943,-74.819 47.877,-71.281 cw(c49.681,-69.337) 49.921,-66.696 66.685,-66.696 65.923,-68.982 ; 45.465,-66.449 cw(c47.891,-67.42) 48.128,-64.817 ; 45.504,-66.417 41.158,-77.312 60.481,-77.312 ccw(c60.729,-74.578) 63.279,-75.597 ; 47.244,-70.352 52.666,-76.608 ; 47.498,-70.352 52.803,-76.473 ; 47.498,-70.098 52.803,-76.219 ; 47.596,-68.982 60.589,-68.982 ; 47.625,-69.971 52.93,-76.092 ; 47.752,-69.844 53.057,-75.965 ; 47.879,-69.717 53.184,-75.838 ; 48.006,-69.59 53.311,-75.711 ; 48.061,-67.637 53.366,-73.758 ; 48.129,-64.818 67.579,-64.818 63.28,-75.595 ; 48.133,-69.463 53.384,-75.521 ; 48.133,-69.209 53.438,-75.33 ; 48.133,-68.955 53.438,-75.076 ; 48.133,-68.066 53.438,-74.187 ; 48.26,-68.828 53.565,-74.949 ; 48.26,-68.447 53.565,-74.568 ; 49.632,-74.832 ccw(c49.737,-74.297) 50.034,-73.84 ; 50.718,-68.969 ccw(c50.692,-69.536) 50.362,-69.998 52.727,-72.727 cw(c50.923,-74.671) 51.656,-77.22 ; 57,-77.108 59.889,-68.728 ; 57.222,-77.058 60.091,-68.737 ; 57.349,-77.058 60.218,-68.737 ; 57.603,-77.058 60.472,-68.737 ; 57.857,-77.058 60.726,-68.737 ; 58.111,-77.058 60.98,-68.737 ; 58.365,-77.058 61.234,-68.737 ; 58.619,-77.058 61.488,-68.737 ; 58.873,-77.058 61.742,-68.737 ; 59.127,-77.058 61.996,-68.737 ; 59.336,-77.108 62.225,-68.728 ; 62.225,-68.982 65.917,-68.982 ; 65.249,-68.98 66.011,-66.694 ; 65.415,-68.982 66.177,-66.696 ; 65.669,-68.982 66.431,-66.696
  lines w0.3: -20.612,-76.198 39.388,-76.198 ; -20.612,-71.198 39.388,-71.198 ; -20.612,-66.198 39.388,-66.198 ; 19.388,-81.198 19.388,-66.198 ; 39.388,-81.198 39.388,-61.198 ; 57,-77.108 59.336,-77.108 ; -20.612,-81.198 69.388,-81.198 69.388,-61.198 -20.612,-61.198 -20.612,-81.198
  text "Project: '.Board_Name'" at -19.612,-64.414 h3
  text "Layer:" at -19.612,-69.498 h3
  text "Gerber:" at 20.377,-69.498 h3
  text "Variant: '.VariantName'" at -19.612,-74.498 h3
  text "'.Board_Reference'" at 20.504,-74.498 h3
  text "R" at 65.884,-76.981 h0.8
  text "Date: '.Board_Document_Date'" at -19.612,-79.498 h3
  text "Rev: '.Board_PCB_Revision'" at 20.447,-79.498 h3
M21-Bottom Sheet Box:
  circle w0.254: c-17.429,-76.219 r1.3
  region: -16.955,-68.982 -1.427,-68.982 -0.733,-70.758 0.478,-71.983 1.875,-70.123 1.875,-68.472 0.732,-67.075 -0.704,-66.696 -16.955,-66.696
  region: -2.951,-77.312 7.805,-77.312 6.811,-74.819 -1.046,-74.819 -1.495,-74.06 -3.704,-76.608
  lines w0.254: -17.468,-66.696 -16.706,-68.982 ; -17.214,-66.696 -16.452,-68.982 ; -17.048,-66.694 -16.286,-68.98 ; -16.96,-68.982 -17.722,-66.696 -0.958,-66.696 cw(c-0.718,-69.337) 1.085,-71.281 -1.981,-74.819 6.811,-74.819 ; -16.955,-68.982 -13.262,-68.982 ; -14.317,-75.595 -18.616,-64.818 0.834,-64.818 ; -14.316,-75.597 ccw(c-11.767,-74.578) -11.518,-77.312 7.805,-77.312 3.458,-66.417 ; -13.262,-68.728 -10.373,-77.108 ; -13.034,-68.737 -10.164,-77.058 ; -12.78,-68.737 -9.91,-77.058 ; -12.526,-68.737 -9.656,-77.058 ; -12.272,-68.737 -9.402,-77.058 ; -12.018,-68.737 -9.148,-77.058 ; -11.764,-68.737 -8.894,-77.058 ; -11.626,-68.982 1.367,-68.982 ; -11.51,-68.737 -8.64,-77.058 ; -11.256,-68.737 -8.386,-77.058 ; -11.129,-68.737 -8.259,-77.058 ; -10.926,-68.728 -8.037,-77.108 ; -4.602,-74.949 0.703,-68.828 ; -4.602,-74.568 0.703,-68.447 ; -4.475,-75.33 0.83,-69.209 ; -4.475,-75.076 0.83,-68.955 ; -4.475,-74.187 0.83,-68.066 ; -4.421,-75.521 0.83,-69.463 ; -4.403,-73.758 0.902,-67.637 ; -4.348,-75.711 0.957,-69.59 ; -4.221,-75.838 1.084,-69.717 ; -4.094,-75.965 1.211,-69.844 ; -3.967,-76.092 1.338,-69.971 ; -3.84,-76.473 1.465,-70.352 ; -3.84,-76.219 1.465,-70.098 ; -3.704,-76.608 1.719,-70.352 ; -2.693,-77.22 cw(c-1.96,-74.671) -3.764,-72.727 -1.399,-69.998 ccw(c-1.73,-69.536) -1.756,-68.969 ; -1.072,-73.84 ccw(c-0.774,-74.297) -0.669,-74.832 ; 0.835,-64.817 cw(c1.071,-67.42) 3.497,-66.449
  lines w0.3: -10.373,-77.108 -8.037,-77.108 ; 9.388,-81.198 9.388,-61.198 ; 9.388,-76.198 69.388,-76.198 ; 9.388,-71.198 69.388,-71.198 ; 9.388,-66.198 69.388,-66.198 ; 29.388,-81.198 29.388,-66.198 ; -20.612,-81.198 -20.612,-61.198 69.388,-61.198 69.388,-81.198 -20.612,-81.198
  text "Project: '.Board_Name'" at 68.194,-64.414 h3
  text "Gerber:" at 28.205,-69.498 h3
  text "Layer:" at 68.193,-69.498 h3
  text "'.Board_Reference'" at 28.205,-74.498 h3
  text "Variant: '.VariantName'" at 68.194,-74.498 h3
  text "R" at -16.921,-76.981 h0.8
  text "Rev: '.Board_PCB_Revision'" at 28.262,-79.498 h3
  text "Date: '.Board_Document_Date'" at 68.194,-79.498 h3

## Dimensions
28.83,90.72 to 21.17,90.72 on M3-Top Dimensions
46,15 to 46,91 on M3-Top Dimensions
4,91 to 46,91 on M3-Top Dimensions
-30.14,18.73 to -30.14,88.73 on M5-Top Constraints
0,94 to 50,1 on M2-Board Dimensions
49,0 to 49,95 on M2-Board Dimensions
